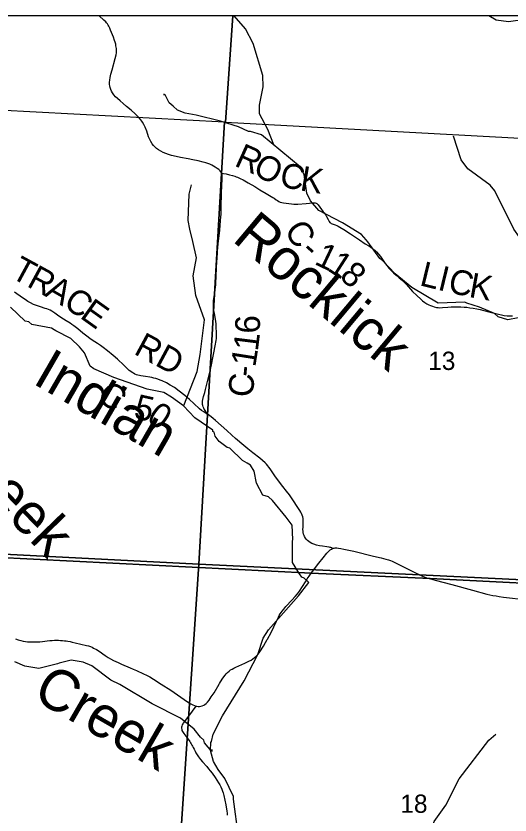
# Model space of a CAD drawing. Extents: x -2.1 to 31.9, y 6.3 to 28.3.
# Drawn here: x 2.128 to 3.259, y 25.414 to 27.244 of the extents above; entities that cross this region are included whole.
import ezdxf

# ---------------------------------------------------------------- set-up
doc = ezdxf.new("R2010")
doc.units = 0
for name, color, linetype in [('Default', 7, 'Continuous'), ('GM_X_County_Road', 7, 'Continuous'), ('GM_X_County_Road_Text', 7, 'Continuous'), ('GM_X_Minor_River', 7, 'Continuous'), ('GM_X_Minor_River_Text', 7, 'Continuous'), ('GM_X_Section', 7, 'Continuous'), ('GM_X_Section_Text', 7, 'Continuous'), ('GM_X_State_Route', 7, 'Continuous'), ('SH_Cut_Line', 7, 'Continuous')]:
    doc.layers.add(name, color=color, linetype=linetype)

msp = doc.modelspace()

# ---------------------------------------------------------------- linework, layer by layer
at = {"layer": 'Default'}
msp.add_lwpolyline([(4.7331, 27.244), (0.0344, 27.244), (0.0344, 26.1105), (0.4641, 26.0883), (2.0757, 26.0047), (2.8034, 25.9683), (3.0763, 25.9555), (3.8625, 25.9158)], dxfattribs=at)
for points in [[(2.6242, 27.244), (1.5768, 27.244), (1.5695, 27.0562), (2.6051, 27.0012), (2.6077, 27.001)], [(3.6804, 27.244), (2.6242, 27.244), (2.6077, 27.001), (3.6616, 26.9432)], [(0.0344, 26.1105), (0.0344, 20.444), (3.7533, 20.444), (3.8489, 20.5389), (3.9894, 20.6326), (4.16, 20.7203), (4.2895, 20.7662), (4.3023, 20.7658), (4.3091, 20.8714), (4.3751, 21.8979), (4.4168, 22.5238), (4.4383, 22.8067), (4.4651, 23.2405), (4.4901, 23.6442), (4.5473, 24.5954), (4.5667, 24.9084), (4.6032, 25.4816), (4.6286, 25.8765), (3.8625, 25.9158), (3.0763, 25.9555), (2.8034, 25.9683), (2.0757, 26.0047), (0.4641, 26.0883)]]:
    msp.add_lwpolyline(points, close=True, dxfattribs=at)
at = {"layer": 'GM_X_County_Road'}
for points in [[(2.5638, 26.3331), (2.5635, 26.3346), (2.5631, 26.3366), (2.5625, 26.3382), (2.5617, 26.3396), (2.5589, 26.3438), (2.5576, 26.3459), (2.5563, 26.3489), (2.5554, 26.3517), (2.5548, 26.3546), (2.5546, 26.3579), (2.5548, 26.3616), (2.5555, 26.3658), (2.5573, 26.373), (2.5598, 26.3818), (2.5619, 26.389), (2.5663, 26.4069), (2.572, 26.4303), (2.5762, 26.4489), (2.5784, 26.4608), (2.5805, 26.4728), (2.5834, 26.4887), (2.5858, 26.5005), (2.5867, 26.5052), (2.5869, 26.5081), (2.5871, 26.5113), (2.5871, 26.5171), (2.5862, 26.5333), (2.5858, 26.5388), (2.5853, 26.5443), (2.5844, 26.5497), (2.582, 26.5629), (2.5801, 26.5728), (2.5797, 26.5768), (2.5796, 26.5802), (2.5796, 26.5836), (2.5799, 26.5875), (2.5802, 26.5921), (2.5807, 26.5967), (2.5813, 26.6014), (2.5822, 26.6062), (2.5839, 26.6176), (2.5845, 26.6231), (2.585, 26.6277), (2.5854, 26.6323), (2.5861, 26.6482), (2.5871, 26.6673), (2.5878, 26.6809), (2.5882, 26.689), (2.5884, 26.6933), (2.5887, 26.6983), (2.5892, 26.7051), (2.5899, 26.7131), (2.5909, 26.7223), (2.5942, 26.7537), (2.5961, 26.7756), (2.5967, 26.7831), (2.5971, 26.7904), (2.5976, 26.8092), (2.5985, 26.8351), (2.5993, 26.8586), (2.5997, 26.8675), (2.6, 26.8743), (2.5999, 26.8778), (2.5995, 26.8809), (2.5985, 26.8841), (2.5969, 26.8867), (2.5951, 26.8891), (2.5921, 26.8921), (2.5885, 26.8949), (2.5834, 26.8981), (2.5797, 26.9002), (2.5757, 26.9024), (2.5715, 26.9044), (2.567, 26.9061), (2.5623, 26.9076), (2.5561, 26.9094), (2.5448, 26.9119), (2.5329, 26.9145), (2.5217, 26.9166), (2.5042, 26.92), (2.4945, 26.9222), (2.484, 26.9248), (2.4769, 26.9268), (2.4706, 26.929), (2.4643, 26.9316), (2.4593, 26.9342), (2.454, 26.9374), (2.4495, 26.9407), (2.4458, 26.944), (2.4428, 26.9472), (2.4393, 26.9515), (2.436, 26.9568), (2.4338, 26.9612), (2.4314, 26.967), (2.4269, 26.9799), (2.4234, 26.9892), (2.4206, 26.9954), (2.4174, 27.0007), (2.4156, 27.0034), (2.4138, 27.0058), (2.4097, 27.0105), (2.4004, 27.0196), (2.3913, 27.0281), (2.3809, 27.037), (2.3729, 27.0439), (2.366, 27.0496), (2.36, 27.0547), (2.3556, 27.059), (2.3515, 27.0637), (2.3486, 27.0677), (2.3465, 27.0715), (2.3447, 27.0754), (2.343, 27.0801), (2.3422, 27.0841), (2.3418, 27.0874), (2.3417, 27.0924), (2.3422, 27.0973), (2.3431, 27.1028), (2.3451, 27.1107), (2.3479, 27.1209), (2.3549, 27.1466), (2.3568, 27.1551), (2.3574, 27.1594), (2.3576, 27.1625), (2.3577, 27.1662), (2.3575, 27.1693), (2.3571, 27.1724), (2.3566, 27.1757), (2.3559, 27.1791), (2.3547, 27.1837), (2.3534, 27.1881), (2.3506, 27.1957), (2.344, 27.2118), (2.3422, 27.2163), (2.3403, 27.2203), (2.3387, 27.2229), (2.337, 27.2256), (2.3349, 27.2281), (2.333, 27.2303), (2.3286, 27.2346), (2.3177, 27.244)], [(2.5985, 26.8841), (2.6028, 26.8836), (2.6092, 26.8822), (2.6167, 26.8803), (2.6234, 26.8785), (2.6286, 26.877), (2.632, 26.8759), (2.6352, 26.8747), (2.6379, 26.8736), (2.641, 26.872), (2.6476, 26.8685), (2.6593, 26.8618), (2.6743, 26.8532), (2.6863, 26.8457), (2.7007, 26.8372), (2.7119, 26.8309), (2.7156, 26.8285), (2.7189, 26.8264), (2.7231, 26.8232), (2.7261, 26.8211), (2.7293, 26.8193), (2.7329, 26.818), (2.7361, 26.8171), (2.74, 26.8164), (2.7589, 26.8139), (2.764, 26.8133), (2.7691, 26.8131), (2.7734, 26.8132), (2.7918, 26.8146), (2.8077, 26.8161), (2.8097, 26.8163), (2.8115, 26.8163), (2.8131, 26.8162), (2.8148, 26.8157), (2.8162, 26.8149), (2.8174, 26.8139), (2.8197, 26.8113), (2.8237, 26.806), (2.8314, 26.7958), (2.8334, 26.7931), (2.8354, 26.7901), (2.8372, 26.7875), (2.8388, 26.7846), (2.8423, 26.7778), (2.8449, 26.7735), (2.8463, 26.7714), (2.8478, 26.7701), (2.8494, 26.769), (2.8517, 26.7679), (2.8588, 26.7655), (2.8622, 26.7642), (2.8656, 26.7627), (2.8693, 26.7606), (2.8784, 26.7547), (2.8938, 26.7448), (2.9139, 26.7313), (2.9275, 26.7225), (2.9355, 26.7177), (2.9403, 26.7145), (2.944, 26.7118), (2.9472, 26.7094), (2.9501, 26.7069), (2.9531, 26.7039), (2.9574, 26.6989), (2.962, 26.6929), (2.9733, 26.6771), (2.9773, 26.6718), (2.9817, 26.6665), (2.9868, 26.6611), (2.9921, 26.6559), (2.9981, 26.6504), (3.0049, 26.6446), (3.0125, 26.6381), (3.0168, 26.6341), (3.0213, 26.6296), (3.0263, 26.624), (3.0356, 26.6134), (3.0454, 26.6036), (3.0546, 26.5952), (3.0588, 26.5917), (3.064, 26.5877), (3.0682, 26.5852), (3.0728, 26.5826), (3.077, 26.5807), (3.0812, 26.5792), (3.0855, 26.5778), (3.0904, 26.5767), (3.0941, 26.5762), (3.0985, 26.576), (3.1041, 26.5762), (3.1163, 26.5773), (3.1241, 26.5779), (3.1321, 26.5782), (3.1393, 26.5783), (3.1467, 26.578), (3.1542, 26.5775), (3.1602, 26.5769), (3.1667, 26.576), (3.1745, 26.5747), (3.183, 26.5731), (3.1905, 26.5715), (3.1992, 26.5694), (3.2133, 26.5657), (3.2326, 26.5608), (3.2395, 26.5593), (3.2457, 26.5583), (3.2525, 26.5575), (3.2585, 26.5573), (3.2643, 26.5575)], [(2.8525, 26.0246), (2.8504, 26.0258), (2.8486, 26.0267), (2.8469, 26.0272), (2.8451, 26.0275), (2.8393, 26.0283), (2.8295, 26.0296), (2.8224, 26.0308), (2.8157, 26.0325), (2.8097, 26.0344), (2.805, 26.0363), (2.8011, 26.0384), (2.7979, 26.0405), (2.795, 26.043), (2.7928, 26.0453), (2.7905, 26.0484), (2.7885, 26.0517), (2.7872, 26.0546), (2.7861, 26.0577), (2.7854, 26.061), (2.7849, 26.0642), (2.7848, 26.0684), (2.7849, 26.0733), (2.7854, 26.0836), (2.7854, 26.0888), (2.7851, 26.0935), (2.7844, 26.0974), (2.7832, 26.1011), (2.7818, 26.1045), (2.7798, 26.108), (2.7776, 26.1117), (2.7716, 26.1209), (2.7629, 26.1336), (2.7538, 26.1471), (2.747, 26.1562), (2.7386, 26.1669), (2.7289, 26.1792), (2.72, 26.1909), (2.7095, 26.2067), (2.707, 26.2105), (2.7044, 26.2137), (2.7013, 26.2173), (2.6979, 26.2207), (2.692, 26.2258), (2.6859, 26.2311), (2.6699, 26.2438), (2.6583, 26.2531), (2.6491, 26.2606), (2.6302, 26.2768), (2.622, 26.2843), (2.6105, 26.2948), (2.5848, 26.3178), (2.5793, 26.3223), (2.5742, 26.3263), (2.5682, 26.3303), (2.5638, 26.3331), (2.5631, 26.3336), (2.5575, 26.3372), (2.5527, 26.3407), (2.5482, 26.3444), (2.5351, 26.3564), (2.5247, 26.3658), (2.5139, 26.3748), (2.5012, 26.3852), (2.4904, 26.3929), (2.4809, 26.3989), (2.4725, 26.4037), (2.4627, 26.4084), (2.4576, 26.4104), (2.4526, 26.4123), (2.4482, 26.4137), (2.4436, 26.4149), (2.4388, 26.416), (2.434, 26.4168), (2.4241, 26.4183), (2.4135, 26.42), (2.4101, 26.4206), (2.4068, 26.4215), (2.4032, 26.4226), (2.3998, 26.424), (2.3967, 26.4258), (2.3934, 26.4278), (2.3903, 26.43), (2.387, 26.4325), (2.3748, 26.4441), (2.36, 26.4583), (2.3501, 26.4668), (2.337, 26.4771), (2.3273, 26.4845), (2.3208, 26.4892), (2.314, 26.4937), (2.3078, 26.4976), (2.302, 26.5013), (2.2963, 26.5052), (2.2897, 26.5104), (2.2807, 26.5178), (2.269, 26.5279), (2.2603, 26.5347), (2.2558, 26.5378), (2.2518, 26.5404), (2.2424, 26.5461), (2.2304, 26.5538), (2.2225, 26.5591), (2.2165, 26.5636), (2.2095, 26.5682), (2.2058, 26.5701), (2.2022, 26.5718), (2.1985, 26.5732), (2.1944, 26.5745), (2.1836, 26.5779), (2.1742, 26.5811), (2.1678, 26.5836), (2.161, 26.5868), (2.155, 26.5902), (2.1482, 26.5945), (2.1421, 26.5987), (2.1238, 26.6116)], [(2.5397, 25.6637), (2.5224, 25.6403), (2.5108, 25.6249), (2.5097, 25.623), (2.5083, 25.6206), (2.5074, 25.6181), (2.5069, 25.6156), (2.5068, 25.6129)], [(2.5068, 25.6129), (2.5071, 25.6104), (2.5077, 25.6081), (2.5088, 25.6058), (2.5101, 25.6035), (2.5122, 25.6007), (2.5192, 25.5915), (2.5239, 25.585), (2.5255, 25.5827), (2.5274, 25.5799), (2.529, 25.5773), (2.5306, 25.5745), (2.532, 25.5719), (2.5337, 25.5686), (2.5355, 25.5647), (2.5377, 25.5603), (2.5396, 25.5565), (2.5409, 25.5541), (2.5425, 25.5518), (2.5457, 25.5473), (2.5502, 25.5417), (2.5547, 25.5362), (2.5644, 25.525), (2.5681, 25.5204), (2.5725, 25.5152), (2.5767, 25.5098), (2.584, 25.4999), (2.5876, 25.4944), (2.5915, 25.488), (2.5941, 25.4834), (2.5964, 25.4787), (2.5986, 25.4737), (2.6003, 25.4691), (2.6017, 25.4648), (2.6033, 25.4593), (2.6057, 25.4485), (2.608, 25.4373), (2.609, 25.4325), (2.6098, 25.4281), (2.6105, 25.4234), (2.611, 25.4185), (2.6113, 25.4136)]]:
    msp.add_lwpolyline(points, dxfattribs=at)
at = {"layer": 'GM_X_Minor_River'}
for points in [[(2.718, 26.9487), (2.7044, 26.984), (2.6852, 27.0196), (2.6855, 27.0397), (2.6939, 27.0819), (2.693, 27.1073), (2.6709, 27.1813), (2.6533, 27.2146), (2.6269, 27.244)], [(3.4872, 27.244), (3.4836, 27.2407), (3.463, 27.2341), (3.4549, 27.2283), (3.4369, 27.2209), (3.4112, 27.2191), (3.3695, 27.2272), (3.3374, 27.2286), (3.2937, 27.2357), (3.2558, 27.2305), (3.2272, 27.2344), (3.2108, 27.244)], [(2.69, 26.972), (2.6646, 26.9794), (2.66, 26.9797), (2.6374, 26.9903), (2.5961, 27.0031), (2.5402, 27.0167), (2.5148, 27.0212), (2.4978, 27.028), (2.4872, 27.0371), (2.4785, 27.0451), (2.4694, 27.0633), (2.4664, 27.0648), (2.4672, 27.0625)], [(3.2778, 26.5528), (3.2536, 26.5478), (3.2317, 26.5553), (3.2234, 26.5626), (3.1893, 26.5773), (3.1602, 26.586), (3.1553, 26.5886), (3.0948, 26.5866), (3.0339, 26.6225), (2.9957, 26.6536), (2.9669, 26.6843), (2.9609, 26.6885), (2.9332, 26.7268), (2.9298, 26.731), (2.9189, 26.7435), (2.8754, 26.7704), (2.8213, 26.7988), (2.802, 26.8204), (2.794, 26.8386), (2.7872, 26.8812), (2.7785, 26.8983), (2.69, 26.972)], [(3.3127, 26.5563), (3.3165, 26.5664), (3.3037, 26.6119), (3.3059, 26.6848), (3.3008, 26.7068), (3.2939, 26.7189), (3.2679, 26.7556), (3.2241, 26.8439), (3.2137, 26.8564), (3.1623, 26.8937), (3.1473, 26.9149), (3.1299, 26.9687)], [(2.512, 26.352), (2.5424, 26.4297), (2.5492, 26.4686), (2.5596, 26.5484), (2.5397, 26.6041), (2.5331, 26.6487), (2.5412, 26.6902), (2.5325, 26.7277), (2.5254, 26.7561), (2.5222, 26.7755), (2.524, 26.8362), (2.5292, 26.857)], [(2.4838, 26.3711), (2.466, 26.3817), (2.4282, 26.3896), (2.3514, 26.4164), (2.306, 26.4357), (2.2973, 26.4421), (2.2841, 26.4725), (2.2727, 26.4861), (2.2534, 26.5055), (2.2186, 26.5233), (2.2148, 26.5255), (2.2088, 26.5293), (2.1642, 26.5372), (2.1566, 26.5433), (2.1487, 26.5451), (2.115, 26.5774)], [(2.6375, 25.365), (2.626, 25.4509), (2.626, 25.4566), (2.606, 25.498), (2.5904, 25.5184), (2.5798, 25.5367), (2.5734, 25.5617), (2.5738, 25.58), (2.5756, 25.583), (2.579, 25.5994), (2.6002, 25.6412), (2.6504, 25.7215), (2.6817, 25.7821), (2.6937, 25.819), (2.7062, 25.8387), (2.7745, 25.9161), (2.7979, 25.9465), (2.7877, 25.9568), (2.7821, 25.9587), (2.7768, 25.9662), (2.7605, 25.9928), (2.7612, 26.0411), (2.7616, 26.0449), (2.7604, 26.0783), (2.7464, 26.0965), (2.715, 26.1345), (2.7055, 26.1432), (2.693, 26.147), (2.6786, 26.1743), (2.6733, 26.202), (2.6646, 26.2153), (2.657, 26.2199), (2.6465, 26.2259), (2.6173, 26.254), (2.6109, 26.2562), (2.5927, 26.2695), (2.584, 26.2816), (2.5814, 26.2911), (2.5787, 26.2923), (2.5783, 26.2957), (2.5371, 26.3241), (2.5114, 26.3514), (2.4838, 26.3711)], [(2.5739, 25.5597), (2.576, 25.564), (2.5757, 25.5598), (2.5594, 25.5792), (2.5579, 25.586), (2.5503, 25.5925), (2.5355, 25.611), (2.5041, 25.6361), (2.4395, 25.669), (2.3657, 25.7129), (2.3449, 25.7231), (2.301, 25.7557), (2.2817, 25.764), (2.2538, 25.7685), (2.2262, 25.7619), (2.2224, 25.7604), (2.1801, 25.7497), (2.1479, 25.7549), (2.1249, 25.7651)], [(2.9487, 25.1342), (2.9532, 25.1511), (2.9808, 25.1996), (2.9978, 25.223), (3.0375, 25.276), (3.0626, 25.3284), (3.0734, 25.3615), (3.0851, 25.3998), (3.112, 25.4366), (3.1422, 25.4975), (3.2102, 25.5853), (3.2265, 25.5996)]]:
    msp.add_lwpolyline(points, dxfattribs=at)
at = {"layer": 'GM_X_Section'}
for points in [[(1.5695, 27.0562), (2.6051, 27.0012), (2.5466, 25.9887), (1.5197, 26.0415)], [(2.6051, 27.0012), (2.6077, 27.001), (3.6616, 26.9432), (3.6038, 25.9379), (2.5466, 25.9887)], [(1.5197, 26.0415), (2.5466, 25.9887), (2.4786, 24.9709), (1.4457, 25.016)], [(2.5466, 25.9887), (3.6038, 25.9379), (3.5328, 24.9185), (2.4786, 24.9709)]]:
    msp.add_lwpolyline(points, close=True, dxfattribs=at)
at = {"layer": 'GM_X_State_Route'}
for points in [[(2.8036, 25.9678), (2.8063, 25.9716), (2.8208, 25.9906), (2.8308, 26.0035), (2.8397, 26.0141), (2.8423, 26.0169), (2.8446, 26.0192), (2.8474, 26.0216), (2.85, 26.0233), (2.8525, 26.0246)], [(2.8525, 26.0246), (2.8543, 26.0252), (2.8564, 26.0256), (2.8584, 26.0258), (2.8604, 26.0258), (2.8624, 26.0258), (2.8663, 26.0254), (2.8712, 26.0247), (2.8785, 26.0234), (2.901, 26.0186), (2.9467, 26.0068), (2.9638, 26.003), (2.9691, 26.0017), (2.9745, 26.0002), (2.9806, 25.9983), (2.9851, 25.9968), (2.9889, 25.9952), (2.997, 25.9917), (2.9998, 25.9903), (3.0104, 25.9852), (3.0364, 25.972), (3.0602, 25.9607), (3.0661, 25.9582), (3.0701, 25.9568), (3.0765, 25.955)], [(2.703, 25.8161), (2.7035, 25.817), (2.7116, 25.8323), (2.7239, 25.8585), (2.7262, 25.8631), (2.7284, 25.8674), (2.7304, 25.8708), (2.7329, 25.8748), (2.7371, 25.8809), (2.7409, 25.8858), (2.7457, 25.8914), (2.7593, 25.9059), (2.7672, 25.9147), (2.7723, 25.9211), (2.7766, 25.9272), (2.7904, 25.9486), (2.7946, 25.9548), (2.7988, 25.9609), (2.8036, 25.9678)], [(3.0765, 25.955), (3.0873, 25.9518), (3.1257, 25.9418), (3.173, 25.9289), (3.2062, 25.9201), (3.213, 25.9185), (3.22, 25.9171), (3.2269, 25.9158), (3.2338, 25.9147), (3.244, 25.9133), (3.2982, 25.907)], [(2.1268, 25.8176), (2.1324, 25.8157), (2.139, 25.8138), (2.1443, 25.8125), (2.149, 25.8117), (2.1542, 25.8112), (2.1598, 25.8109), (2.1746, 25.8109), (2.182, 25.8112), (2.188, 25.8117), (2.1933, 25.8123), (2.1989, 25.8131), (2.2048, 25.8137), (2.2101, 25.8141), (2.2159, 25.8143), (2.2204, 25.8144), (2.2251, 25.8143), (2.2293, 25.8141), (2.2337, 25.8139), (2.2384, 25.8134), (2.2424, 25.8129), (2.2464, 25.8123), (2.2513, 25.8114), (2.2564, 25.8102), (2.2631, 25.8086), (2.2889, 25.8025), (2.2933, 25.8014), (2.2979, 25.7999), (2.3017, 25.7985), (2.3052, 25.7967), (2.3116, 25.7932), (2.3179, 25.7893), (2.3316, 25.7798), (2.339, 25.775), (2.3438, 25.7722), (2.351, 25.7684), (2.3616, 25.7633), (2.369, 25.76), (2.389, 25.7513), (2.3958, 25.7483), (2.4033, 25.7452), (2.4196, 25.7377), (2.4268, 25.7342), (2.4339, 25.7304), (2.4424, 25.7253), (2.4603, 25.7142), (2.4823, 25.7001), (2.5205, 25.6735), (2.5278, 25.6688), (2.5323, 25.6664), (2.5364, 25.6648), (2.5397, 25.6637), (2.5419, 25.6632), (2.5444, 25.6629), (2.5477, 25.6629), (2.5509, 25.6633), (2.554, 25.6642), (2.5576, 25.6657), (2.5602, 25.6675), (2.5632, 25.67), (2.5658, 25.6727), (2.5698, 25.6776), (2.5749, 25.6847), (2.5812, 25.694), (2.593, 25.7138), (2.594, 25.7154)], [(2.594, 25.7154), (2.6, 25.725), (2.6036, 25.7305), (2.6064, 25.7343), (2.6088, 25.7372), (2.6117, 25.7404), (2.6154, 25.7436), (2.6191, 25.7465), (2.6225, 25.7485), (2.6261, 25.7505), (2.6314, 25.7529), (2.6518, 25.7619), (2.6609, 25.7662), (2.6658, 25.7689), (2.67, 25.7718), (2.674, 25.7747), (2.6777, 25.7779), (2.6819, 25.7825), (2.6862, 25.7883), (2.6944, 25.8012), (2.6989, 25.8091), (2.703, 25.8161)]]:
    msp.add_lwpolyline(points, dxfattribs=at)
at = {"layer": 'SH_Cut_Line'}
msp.add_lwpolyline([(6.8344, 20.444), (6.8344, 27.244), (0.0344, 27.244), (0.0344, 20.444)], dxfattribs=at)

# ---------------------------------------------------------------- texts
at = {"layer": 'GM_X_County_Road_Text'}
for s, height, rotation, p in [('R', 0.0568, 335.7221, (2.6254, 26.902)), ('O', 0.0568, 332.0338, (2.6671, 26.8832)), ('C', 0.0568, 349.6234, (2.7292, 26.8536)), ('K', 0.0568, 350.4358, (2.776, 26.845)), ('C', 0.0568, 303.6154, (2.7402, 26.7528)), ('-', 0.0568, 318.5246, (2.7766, 26.7018)), ('1', 0.0568, 334.5372, (2.8085, 26.6768)), ('T', 0.0568, 331.5142, (2.1127, 26.6464)), ('1', 0.0568, 327.2301, (2.8384, 26.6627)), ('8', 0.0568, 318.2232, (2.866, 26.6452)), ('L', 0.0568, 346.3286, (3.0498, 26.6276)), ('R', 0.0568, 331.4553, (2.15, 26.6261)), ('I', 0.0568, 346.3273, (3.0911, 26.6176)), ('C', 0.0568, 347.0681, (3.1145, 26.6119)), ('A', 0.0568, 329.9809, (2.1907, 26.604)), ('K', 0.0568, 349.7534, (3.1629, 26.6008)), ('C', 0.0568, 326.58, (2.2332, 26.5794)), ('E', 0.0568, 324.4262, (2.2717, 26.5541)), ('6', 0.0568, 89.1677, (2.6861, 26.5164)), ('RD', 0.05682, 331.6659, (2.3951, 26.4714)), ('1', 0.0568, 82.8945, (2.6813, 26.4749)), ('1', 0.0568, 81.0335, (2.6755, 26.4384)), ('-', 0.0568, 84.6766, (2.6735, 26.4161)), ('C', 0.0568, 86.3678, (2.6705, 26.37)), ('C', 0.0568, 321.4094, (2.3096, 26.3691)), ('5', 0.0568, 347.4153, (2.3951, 26.3232)), ('-', 0.0568, 348.5859, (2.3725, 26.3277)), ('0', 0.0568, 325.0216, (2.4239, 26.3179))]:
    msp.add_text(s, height=height, rotation=rotation, dxfattribs=at).set_placement(p)
at = {"layer": 'GM_X_Minor_River_Text'}
for s, height, rotation, p in [('Rocklick', 0.0947, 319.9998, (2.6204, 26.7302)), ('Indian', 0.0947, 330.0018, (2.1629, 26.4039)), ('Creek', 0.0947, 314.0019, (1.9654, 26.2414)), ('Creek', 0.09469, 330.0049, (2.1622, 25.6821))]:
    msp.add_text(s, height=height, rotation=rotation, dxfattribs=at).set_placement(p)
at = {"layer": 'GM_X_Section_Text'}
for s, p in [('13', (3.0716, 26.4334)), ('18', (3.0078, 25.4193))]:
    msp.add_text(s, height=0.04186, rotation=0, dxfattribs=at).set_placement(p)

doc.saveas('drawing.dxf')
